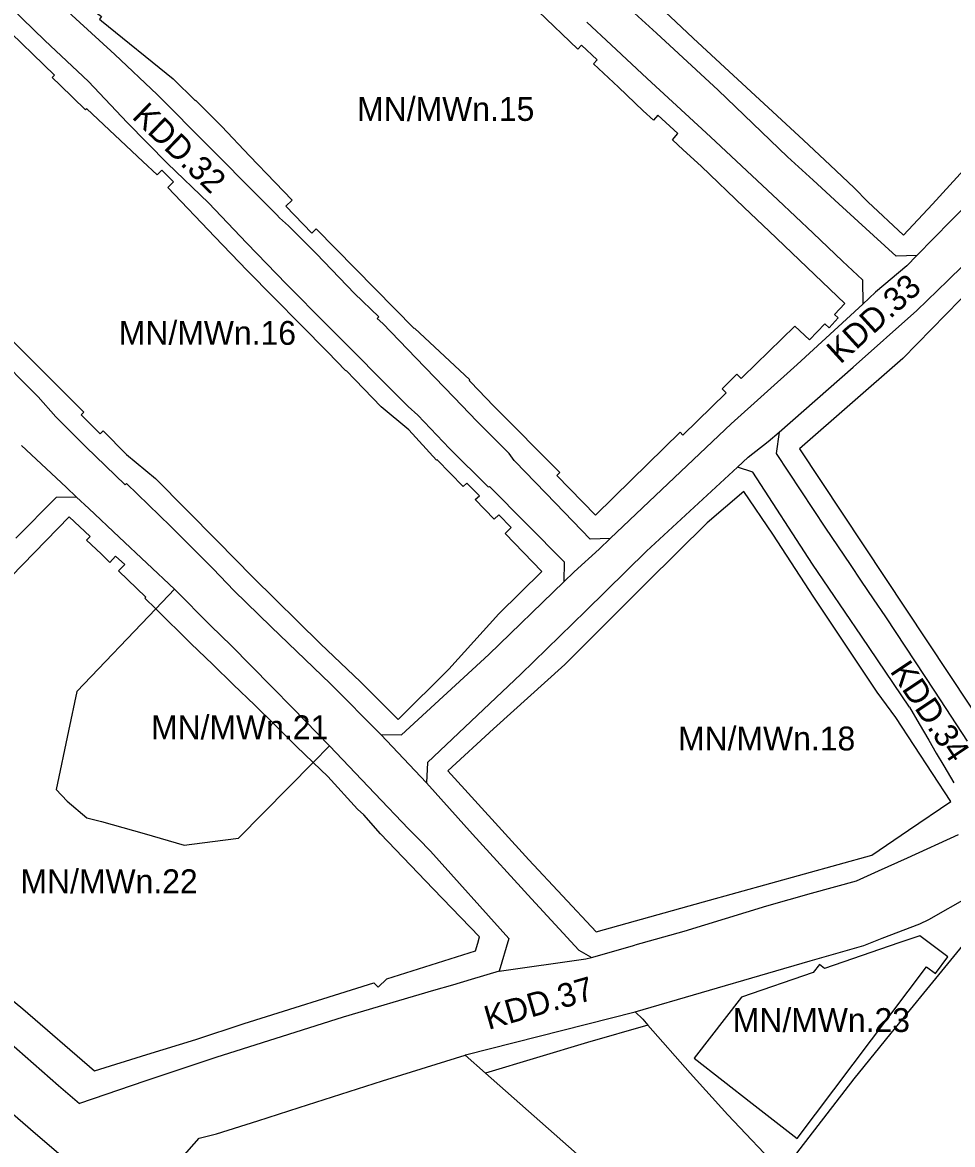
# Model space of a CAD drawing. Extents: x 7425067 to 7426806, y 5549054 to 5550619.
# Drawn here: x 7426346.6 to 7426541.6, y 5549247.2 to 5549482.5 of the extents above; entities that cross this region are included whole.
import ezdxf

# ---------------------------------------------------------------- set-up
doc = ezdxf.new("R2010")
doc.units = 0
for name, color, linetype in [('LIN_Linia Zabudowy Nieprzekraczalna', 7, 'Continuous'), ('LIN_linie_rozgraniczajace', 7, 'Continuous'), ('TXT_Oznaczenia_przeznaczen', 7, 'Continuous')]:
    doc.layers.add(name, color=color, linetype=linetype)

msp = doc.modelspace()

# ---------------------------------------------------------------- linework, layer by layer
at = {"layer": 'LIN_Linia Zabudowy Nieprzekraczalna'}
for points in [[(7426412.8563, 5549581.6544), (7426396.03, 5549563.69), (7426404.67, 5549555.61), (7426420.91, 5549541.33), (7426423.35, 5549539.08), (7426424.73, 5549537.74), (7426431.3126, 5549531.6576), (7426439.18, 5549524.38), (7426447.81, 5549516.35), (7426457.06, 5549507.81), (7426459.86, 5549505.23), (7426466.65, 5549498.95), (7426473.46, 5549492.05), (7426482.4, 5549483.78), (7426487.2, 5549479.22), (7426492.88, 5549473.96), (7426510.35, 5549457.84), (7426515.95, 5549452.58), (7426520.98, 5549447.85), (7426523.82, 5549444.93), (7426531.3, 5549437.91), (7426537.37, 5549444.38), (7426550.43, 5549458.71), (7426562.87, 5549471.53)], [(7426388.01, 5549547.25), (7426379.73, 5549538.35), (7426370.82, 5549524.17), (7426365.2, 5549516.56), (7426358.3, 5549507.38), (7426353.55, 5549500.8), (7426352.92, 5549501.26), (7426348.36, 5549494.93), (7426351.28, 5549492.83), (7426351.09, 5549492.57), (7426354.41, 5549490), (7426353.97, 5549489.41), (7426356.55, 5549487.37), (7426357.22, 5549488.15), (7426363.12, 5549483.75), (7426362.74, 5549483.17), (7426363.13, 5549482.88), (7426378.18, 5549470.72), (7426382.81, 5549466.07), (7426382.87, 5549466.2), (7426388.4, 5549460.7), (7426394.14, 5549454.53), (7426399.56, 5549448.92), (7426403.0973, 5549445.2587)], [(7426463.77, 5549477.75), (7426463.02, 5549476.94), (7426454.68, 5549484.87), (7426448, 5549491.22)], [(7426359.7724, 5549464.1559), (7426354.45, 5549469.35), (7426352.79, 5549470.97), (7426353.26, 5549471.45), (7426341.89, 5549482.48)], [(7426518.98, 5549423.56), (7426503.16, 5549438.73), (7426497.87, 5549443.72), (7426488.85, 5549452.34), (7426485.12, 5549455.82), (7426482.83, 5549457.91), (7426484, 5549459.2), (7426479.81, 5549463.04), (7426478.86, 5549461.99), (7426476.71, 5549463.96), (7426471.51, 5549468.97), (7426466.3, 5549473.8), (7426467.09, 5549474.67), (7426463.77, 5549477.75)], [(7426374.8003, 5549450.561), (7426371.83, 5549453.35), (7426360.03, 5549464.43), (7426359.7724, 5549464.1559)], [(7426578.2334, 5549459.8051), (7426569.97, 5549451.42), (7426565.8696, 5549447.2625), (7426564.6682, 5549446.0444), (7426564.47, 5549446.27), (7426555.42, 5549438.32), (7426556.1878, 5549437.4461), (7426548.28, 5549429.46), (7426546.95, 5549430.68), (7426546.28, 5549431.38), (7426544.7347, 5549429.8853), (7426544.5, 5549430.11), (7426543.66, 5549429.31), (7426543.8802, 5549429.0898), (7426544.54, 5549428.32), (7426544.93, 5549428.66), (7426546.18, 5549427.43), (7426531.16, 5549412.07)], [(7426374.8003, 5549450.561), (7426375.79, 5549451.54), (7426378.24, 5549449.06), (7426377.0629, 5549447.8996)], [(7426421.77, 5549401.9), (7426416.29, 5549407.59), (7426414.42, 5549409.53), (7426414.34, 5549409.46), (7426410.49, 5549413.45), (7426393.71, 5549430.5), (7426386.89, 5549437.54), (7426377.0629, 5549447.8996)], [(7426403.0973, 5549445.2587), (7426401.77, 5549443.97), (7426407.24, 5549438.31)], [(7426408.1593, 5549439.2018), (7426407.24, 5549438.31)], [(7426408.1593, 5549439.2018), (7426428.67, 5549418.33), (7426428.7524, 5549418.4085)], [(7426331.6023, 5549428.5271), (7426359.43, 5549400.79), (7426358.89, 5549400.25), (7426362.88, 5549396.28), (7426363.45, 5549396.86), (7426368.41, 5549391.92), (7426374.46, 5549386.85), (7426387.42, 5549373.83), (7426394.89, 5549366.23), (7426409.06, 5549352.23), (7426417.45, 5549344.27), (7426425.33, 5549336.34)], [(7426508.5333, 5549418.8367), (7426511.6, 5549415.93), (7426514.81, 5549419.32), (7426515.68, 5549418.5), (7426517.61, 5549420.54), (7426516.83, 5549421.29), (7426518.98, 5549423.56)], [(7426428.7524, 5549418.4085), (7426440.38, 5549407.56)], [(7426484.4584, 5549396.5923), (7426485.05, 5549395.99), (7426494.08, 5549404.86), (7426493.26, 5549405.69), (7426496.38, 5549408.75), (7426497.26, 5549407.86), (7426497.64, 5549408.23), (7426508.5333, 5549418.8367)], [(7426531.16, 5549412.07), (7426509.4701, 5549393.1024)], [(7426440.38, 5549407.56), (7426440.2455, 5549407.4136)], [(7426440.2455, 5549407.4136), (7426440.48, 5549407.17), (7426445.38, 5549402.08), (7426459.2611, 5549388.1296)], [(7426455.49, 5549367.38), (7426447.74, 5549375.32), (7426449.05, 5549376.59), (7426446.45, 5549379.26), (7426445.5, 5549378.33), (7426441.5, 5549382.47), (7426442.37, 5549383.28), (7426439.75, 5549385.94), (7426438.96, 5549385.22), (7426433.5332, 5549390.8134), (7426433.41, 5549390.7), (7426427.56, 5549397.06), (7426421.77, 5549401.9)], [(7426466.7045, 5549379.1808), (7426474.29, 5549386.62), (7426484.4584, 5549396.5923)], [(7426509.4701, 5549393.1024), (7426549.7, 5549332.54), (7426559.05, 5549338.85)], [(7426459.2611, 5549388.1296), (7426458.59, 5549387.48), (7426466.7045, 5549379.1808)], [(7426541.22, 5549319.16), (7426529.66, 5549336.76), (7426525.75, 5549342.06), (7426512.47, 5549362.01), (7426503.87, 5549375.23), (7426497.8, 5549384.17), (7426490.12, 5549377.56)], [(7426356.3766, 5549378.8485), (7426319.69, 5549341.18), (7426308.92, 5549329.51), (7426298.8, 5549319.16)], [(7426372.44, 5549362.03), (7426366.71, 5549367.54), (7426368, 5549368.88), (7426366.1, 5549370.61), (7426364.9, 5549369.29), (7426363.03, 5549371.08), (7426360.01, 5549373.92), (7426360.76, 5549374.71), (7426356.3766, 5549378.8485)], [(7426490.12, 5549377.56), (7426477.46, 5549365.11), (7426460.29, 5549347.91), (7426445.33, 5549334.36), (7426435.73, 5549325.61)], [(7426425.33, 5549336.34), (7426435.94, 5549346.9), (7426446.46, 5549358.52), (7426455.49, 5549367.38)], [(7426372.44, 5549362.03), (7426372.1916, 5549361.7762)], [(7426410.6, 5549324.39), (7426407.5057, 5549327.3454), (7426403.92, 5549330.77), (7426399.45, 5549335.24), (7426395.32, 5549339.39), (7426390.77, 5549343.71), (7426386.46, 5549347.89), (7426381.8753, 5549352.3062), (7426374.4973, 5549359.5214), (7426372.1916, 5549361.7762)], [(7426435.73, 5549325.61), (7426452.75, 5549306.93), (7426466.8871, 5549291.8475)], [(7426442.4143, 5549290.7959), (7426440.47, 5549292.81), (7426432.68, 5549300.88), (7426421.62, 5549312.36), (7426418.11, 5549316.34), (7426416.83, 5549317.52), (7426410.6, 5549324.39)], [(7426524.6719, 5549307.929), (7426532.35, 5549313.14), (7426541.22, 5549319.16)], [(7426466.8871, 5549291.8475), (7426489.39, 5549298.11), (7426524.6719, 5549307.929)], [(7426441.5266, 5549287.8438), (7426442.0212, 5549289.4885), (7426442.4143, 5549290.7959)], [(7426540.61, 5549286.56), (7426534.75, 5549290.96), (7426530.34, 5549289.5), (7426514.7426, 5549284.1309), (7426513.69, 5549285), (7426512.3317, 5549283.301), (7426497.31, 5549278.13), (7426487.4162, 5549265.3245)], [(7426361.6902, 5549262.7143), (7426372.65, 5549266.08), (7426382.94, 5549269.24), (7426393.02, 5549272.58), (7426420.2456, 5549281.1472), (7426421.12, 5549280.23), (7426422.9829, 5549282.0085), (7426441.5266, 5549287.8438)], [(7426508.9775, 5549248.4925), (7426528.4283, 5549274.2889), (7426536.12, 5549284.49), (7426537.99, 5549283.08), (7426540.61, 5549286.56)], [(7426336.25, 5549284.23), (7426346.65, 5549275.68), (7426361.6902, 5549262.7143)], [(7426477.6833, 5549272.2774), (7426465.0191, 5549268.6155), (7426443.6501, 5549262.175)], [(7426487.4162, 5549265.3245), (7426499.54, 5549255.86), (7426508.9775, 5549248.4925)]]:
    msp.add_lwpolyline(points, dxfattribs=at)
at = {"layer": 'LIN_linie_rozgraniczajace'}
for points in [[(7426479.49, 5549480.23), (7426466.45, 5549492.21)], [(7426341.6185, 5549488.0696), (7426351.279, 5549478.7147)], [(7426365.92, 5549475.81), (7426355.28, 5549485.53)], [(7426464.9, 5549482.54), (7426469.99, 5549477.79)], [(7426492.46, 5549468.32), (7426479.49, 5549480.23)], [(7426351.279, 5549478.7147), (7426360.4072, 5549470.125)], [(7426374.8, 5549467.38), (7426365.92, 5549475.81)], [(7426469.99, 5549477.79), (7426477.53, 5549470.77)], [(7426477.53, 5549470.77), (7426490.84, 5549458.55)], [(7426360.4072, 5549470.125), (7426368.49, 5549461.52)], [(7426396.27, 5549445.78), (7426374.8, 5549467.38)], [(7426506.99, 5549454.33), (7426492.46, 5549468.32)], [(7426368.49, 5549461.52), (7426376.95, 5549452.96)], [(7426490.84, 5549458.55), (7426504.97, 5549445.34)], [(7426512.375, 5549449.41), (7426506.99, 5549454.33)], [(7426376.95, 5549452.96), (7426385.57, 5549444.7)], [(7426550.6878, 5549450.3164), (7426541.215, 5549440.905)], [(7426517.76, 5549444.49), (7426512.375, 5549449.41)], [(7426399.92, 5549442.15), (7426396.27, 5549445.78)], [(7426504.97, 5549445.34), (7426512.36, 5549438.33)], [(7426385.57, 5549444.7), (7426393.64, 5549436.22)], [(7426525.03, 5549437.855), (7426517.76, 5549444.49)], [(7426400.48, 5549441.54), (7426399.92, 5549442.15)], [(7426402.35, 5549439.83), (7426400.48, 5549441.54)], [(7426541.215, 5549440.905), (7426534.0966, 5549433.6419)], [(7426408.21, 5549433.97), (7426402.35, 5549439.83)], [(7426512.36, 5549438.33), (7426518.54, 5549432.47)], [(7426529.7782, 5549433.5216), (7426525.03, 5549437.855)], [(7426393.64, 5549436.22), (7426401.95, 5549427.65)], [(7426416.21, 5549425.67), (7426408.21, 5549433.97)], [(7426534.0966, 5549433.6419), (7426529.7782, 5549433.5216)], [(7426534.0966, 5549433.6419), (7426531.9954, 5549431.498)], [(7426540.59, 5549428.41), (7426547.1, 5549434.74)], [(7426518.54, 5549432.47), (7426522.67, 5549428.56)], [(7426531.9954, 5549431.498), (7426525.43, 5549425.94)], [(7426522.67, 5549428.56), (7426522.74, 5549423.46)], [(7426534.08, 5549422.09), (7426540.59, 5549428.41)], [(7426401.95, 5549427.65), (7426410.38, 5549419.09)], [(7426421.28, 5549420.76), (7426416.21, 5549425.67)], [(7426525.43, 5549425.94), (7426522.74, 5549423.46)], [(7426522.74, 5549423.46), (7426509.02, 5549410.8)], [(7426520.74, 5549410.25), (7426534.08, 5549422.09)], [(7426410.38, 5549419.09), (7426427.42, 5549401.98)], [(7426420.94, 5549420.45), (7426421.28, 5549420.76)], [(7426422.11, 5549419.39), (7426420.94, 5549420.45)], [(7426429.01, 5549412.16), (7426422.11, 5549419.39)], [(7426340.24, 5549413.65), (7426349.88, 5549404)], [(7426437.01, 5549403.96), (7426429.01, 5549412.16)], [(7426509.02, 5549410.8), (7426495.15, 5549398.32)], [(7426502.93, 5549394.62), (7426505.2058, 5549396.6172), (7426520.74, 5549410.25)], [(7426349.88, 5549404), (7426353.57, 5549399.81)], [(7426441.92, 5549398.86), (7426437.01, 5549403.96)], [(7426427.42, 5549401.98), (7426429.4383, 5549400.165)], [(7426353.57, 5549399.81), (7426359.82, 5549393.51)], [(7426429.4383, 5549400.165), (7426436.0724, 5549393.1488)], [(7426448.63, 5549392.12), (7426441.92, 5549398.86)], [(7426495.15, 5549398.32), (7426480.61, 5549384.56)], [(7426505.2058, 5549396.6172), (7426504.6009, 5549392.0949)], [(7426346.33, 5549393.77), (7426355.73, 5549385.06)], [(7426359.82, 5549393.51), (7426368.118, 5549385.5862)], [(7426436.0724, 5549393.1488), (7426444.18, 5549385.17)], [(7426498.74, 5549391.36), (7426502.93, 5549394.62)], [(7426449.64, 5549390.69), (7426448.63, 5549392.12)], [(7426477.44, 5549371.63), (7426496.4962, 5549389.2816), (7426498.74, 5549391.36)], [(7426504.6009, 5549392.0949), (7426514.96, 5549376.44)], [(7426449.8683, 5549390.4583), (7426449.64, 5549390.69)], [(7426458.3006, 5549381.6994), (7426449.8683, 5549390.4583)], [(7426499.7301, 5549388.1879), (7426496.4962, 5549389.2816)], [(7426512.2107, 5549368.9439), (7426499.7301, 5549388.1879)], [(7426355.73, 5549385.06), (7426357.9104, 5549382.9988)], [(7426368.118, 5549385.5862), (7426368.4, 5549385.83)], [(7426368.4, 5549385.83), (7426377.57, 5549376.91)], [(7426444.18, 5549385.17), (7426444.47, 5549385.24)], [(7426444.47, 5549385.24), (7426460.1474, 5549369.4304)], [(7426480.61, 5549384.56), (7426469.81, 5549374.33)], [(7426353.6206, 5549382.9247), (7426345.17, 5549374.37)], [(7426357.9104, 5549382.9988), (7426353.6206, 5549382.9247)], [(7426357.9104, 5549382.9988), (7426360.485, 5549380.565)], [(7426465.6311, 5549374.1471), (7426458.3006, 5549381.6994)], [(7426360.485, 5549380.565), (7426366.82, 5549374.59)], [(7426377.57, 5549376.91), (7426386.56, 5549367.93)], [(7426366.82, 5549374.59), (7426378.46, 5549363.66)], [(7426469.81, 5549374.33), (7426465.6311, 5549374.1471)], [(7426469.81, 5549374.33), (7426467.45, 5549372.09)], [(7426514.96, 5549376.44), (7426520.14, 5549368.85)], [(7426467.45, 5549372.09), (7426462.26, 5549367.3)], [(7426464.71, 5549359.15), (7426477.44, 5549371.63)], [(7426386.56, 5549367.93), (7426390.8993, 5549363.3952)], [(7426462.26, 5549367.3), (7426460.1027, 5549365.2149), (7426444.33, 5549349.97)], [(7426460.1474, 5549369.4304), (7426460.1027, 5549365.2149)], [(7426522.5133, 5549353.7957), (7426512.2107, 5549368.9439)], [(7426520.14, 5549368.85), (7426522.43, 5549365.35)], [(7426522.43, 5549365.35), (7426524.97, 5549361.625)], [(7426378.46, 5549363.66), (7426374.4973, 5549359.5214), (7426357.96, 5549342.25)], [(7426378.46, 5549363.66), (7426386.06, 5549355.98)], [(7426390.8993, 5549363.3952), (7426398.69, 5549355.75)], [(7426524.97, 5549361.625), (7426527.51, 5549357.9)], [(7426451.06, 5549345.87), (7426464.71, 5549359.15)], [(7426527.51, 5549357.9), (7426537.79, 5549342.29)], [(7426386.06, 5549355.98), (7426390.35, 5549351.85)], [(7426398.69, 5549355.75), (7426411.14, 5549343.82)], [(7426532.56, 5549338.96), (7426522.5133, 5549353.7957)], [(7426390.35, 5549351.85), (7426394.53, 5549347.63)], [(7426444.33, 5549349.97), (7426426.0393, 5549333.1135)], [(7426394.53, 5549347.63), (7426398.84, 5549343.21)], [(7426411.14, 5549343.82), (7426421.7128, 5549333.2059)], [(7426431.4549, 5549327.3372), (7426451.06, 5549345.87)], [(7426357.96, 5549342.25), (7426356.25, 5549334)], [(7426398.84, 5549343.21), (7426403.24, 5549338.7)], [(7426537.79, 5549342.29), (7426544.645, 5549331.83)], [(7426403.24, 5549338.7), (7426410.93, 5549330.82)], [(7426532.56, 5549338.96), (7426534.595, 5549335.475)], [(7426534.595, 5549335.475), (7426536.63, 5549331.99)], [(7426356.25, 5549334), (7426353.66, 5549321.65)], [(7426431.2797, 5549323.0433), (7426421.7128, 5549333.2059)], [(7426421.7128, 5549333.2059), (7426426.0393, 5549333.1135)], [(7426536.63, 5549331.99), (7426538.18, 5549329.325)], [(7426391.87, 5549311.48), (7426407.5057, 5549327.3454), (7426410.93, 5549330.82)], [(7426410.93, 5549330.82), (7426420.45, 5549320.85)], [(7426431.4549, 5549327.3372), (7426431.2797, 5549323.0433)], [(7426538.18, 5549329.325), (7426539.73, 5549326.66)], [(7426539.73, 5549326.66), (7426541.835, 5549323.065)], [(7426431.2797, 5549323.0433), (7426440.9376, 5549312.2935)], [(7426353.66, 5549321.65), (7426355.9377, 5549319.2012)], [(7426420.45, 5549320.85), (7426427.5, 5549313.46)], [(7426355.9377, 5549319.2012), (7426360.05, 5549315.74)], [(7426360.05, 5549315.74), (7426363.13, 5549314.95)], [(7426363.13, 5549314.95), (7426372.11, 5549312.44)], [(7426427.5, 5549313.46), (7426429.59, 5549311.32)], [(7426372.11, 5549312.44), (7426380.5, 5549309.98)], [(7426386.38, 5549310.76), (7426391.87, 5549311.48)], [(7426429.59, 5549311.32), (7426432.0856, 5549308.7677)], [(7426440.9376, 5549312.2935), (7426453.31, 5549298.77)], [(7426542.78, 5549312.14), (7426532.06, 5549307.31)], [(7426380.5, 5549309.98), (7426386.38, 5549310.76)], [(7426432.0856, 5549308.7677), (7426448.5685, 5549290.4263)], [(7426532.06, 5549307.31), (7426525.9533, 5549304.5586)], [(7426525.9533, 5549304.5586), (7426521.34, 5549302.48)], [(7426521.34, 5549302.48), (7426511.97, 5549299.86)], [(7426511.97, 5549299.86), (7426502.6, 5549297.24)], [(7426536.6, 5549294.43), (7426545.2146, 5549299.3138), (7426545.49, 5549299.47)], [(7426453.31, 5549298.77), (7426463.19, 5549287.98)], [(7426502.6, 5549297.24), (7426493.935, 5549294.585)], [(7426493.935, 5549294.585), (7426485.27, 5549291.93)], [(7426534.7, 5549293.51), (7426536.6, 5549294.43)], [(7426539.355, 5549283.58), (7426549.07, 5549295.43)], [(7426526.82, 5549290.51), (7426534.7, 5549293.51)], [(7426448.5685, 5549290.4263), (7426446.51, 5549283.58)], [(7426485.27, 5549291.93), (7426474.99, 5549289.045)], [(7426502.83, 5549283.15), (7426511.76, 5549285.75), (7426522.98, 5549288.99), (7426526.82, 5549290.51)], [(7426463.19, 5549287.98), (7426465.67, 5549286.58)], [(7426465.8482, 5549286.4794), (7426474.99, 5549289.045)], [(7426446.51, 5549283.58), (7426464.71, 5549286.16)], [(7426464.71, 5549286.16), (7426465.8482, 5549286.4794)], [(7426465.67, 5549286.58), (7426465.8482, 5549286.4794)], [(7426446.51, 5549283.58), (7426440.66, 5549281.84)], [(7426475.06, 5549275.03), (7426502.83, 5549283.15)], [(7426529.64, 5549271.73), (7426539.355, 5549283.58)], [(7426436.71, 5549280.68), (7426432.76, 5549279.52)], [(7426440.66, 5549281.84), (7426436.71, 5549280.68)], [(7426432.76, 5549279.52), (7426413.84, 5549273.91)], [(7426413.84, 5549273.91), (7426402.33, 5549270.31)], [(7426439.49, 5549266.01), (7426475.06, 5549275.03)], [(7426476.61, 5549273.5), (7426475.06, 5549275.03)], [(7426476.61, 5549273.5), (7426477.6833, 5549272.2774), (7426486.53, 5549262.2), (7426494.45, 5549253.45), (7426505.87, 5549241.45)], [(7426340.05, 5549271.94), (7426354.14, 5549259.61)], [(7426520.96, 5549261.01), (7426529.64, 5549271.73)], [(7426402.33, 5549270.31), (7426387.14, 5549265.5)], [(7426387.14, 5549265.5), (7426372.22, 5549260.52)], [(7426422.04, 5549260.59), (7426439.39, 5549265.94)], [(7426439.39, 5549265.94), (7426439.49, 5549266.01)], [(7426504.87, 5549208.07), (7426443.6501, 5549262.175), (7426439.39, 5549265.94)], [(7426354.14, 5549259.61), (7426358.49, 5549255.81)], [(7426372.22, 5549260.52), (7426358.49, 5549255.81)], [(7426404.57, 5549254.99), (7426422.04, 5549260.59)], [(7426505.87, 5549241.45), (7426520.96, 5549261.01)], [(7426339.16, 5549258.27), (7426349.305, 5549249.565)], [(7426395.91, 5549252.225), (7426404.57, 5549254.99)], [(7426387.25, 5549249.46), (7426395.91, 5549252.225)], [(7426349.305, 5549249.565), (7426359.45, 5549240.86)], [(7426377.42, 5549241.53), (7426383.61, 5549248.54)], [(7426383.61, 5549248.54), (7426387.25, 5549249.46)]]:
    msp.add_lwpolyline(points, dxfattribs=at)

# ---------------------------------------------------------------- texts
at = {"layer": 'TXT_Oznaczenia_przeznaczen'}
for s, p in [('MN/MWn.15', (7426416.7397, 5549461.8712)), ('MN/MWn.16', (7426366.7659, 5549414.9136)), ('MN/MWn.21', (7426373.5231, 5549332.2129)), ('MN/MWn.18', (7426484.0264, 5549329.8665)), ('MN/MWn.22', (7426346.1473, 5549299.93)), ('MN/MWn.23', (7426495.5027, 5549270.8263))]:
    msp.add_text(s, height=5, dxfattribs=at).set_placement(p)
for s, rotation, p in [('KDD.32', 316.154279, (7426369.3082, 5549462.5353)), ('KDD.33', 42.300164, (7426518.0431, 5549410.7259)), ('KDD.34', 303.67634, (7426528.3359, 5549346.4871)), ('KDD.37', 16.172862, (7426444.2598, 5549271.2452))]:
    msp.add_text(s, height=5, rotation=rotation, dxfattribs=at).set_placement(p)

doc.saveas('drawing.dxf')
